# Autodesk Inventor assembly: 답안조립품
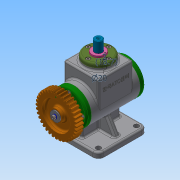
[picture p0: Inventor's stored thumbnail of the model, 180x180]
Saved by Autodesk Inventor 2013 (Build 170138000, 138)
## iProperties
Created: 2019-01
Part Number: 답안조립품
Document SubType Name: Assembly
Designer: Administrator
Author: Administrator
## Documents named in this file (18)
- C:\Users\Administrator\Desktop\390107V1001\답안조립품.iam
- C:\Users\Administrator\Desktop\390107V1001\본체.ipt
- C:\Users\Administrator\Desktop\390107V1001\뒤커버.ipt
- C:\Users\Administrator\Desktop\390107V1001\멈춤링.ipt
- C:\Users\Administrator\Desktop\390107V1001\베어링 6203.ipt
- C:\Users\Administrator\Desktop\390107V1001\볼트 M4.ipt
- C:\Users\Administrator\Desktop\390107V1001\부시.ipt
- C:\Users\Administrator\Desktop\390107V1001\상부커버.ipt
- C:\Users\Administrator\Desktop\390107V1001\스퍼기어.ipt
- C:\Users\Administrator\Desktop\390107V1001\스프링와셔.ipt
- C:\Users\Administrator\Desktop\390107V1001\스프링조립용 와셔.ipt
- C:\Users\Administrator\Desktop\390107V1001\슬라이더.ipt
- C:\Users\Administrator\Desktop\390107V1001\앞커버.ipt
- C:\Users\Administrator\Desktop\390107V1001\오일 실 17 30 5.ipt
- C:\Users\Administrator\Desktop\390107V1001\키 4x4x12.ipt
- C:\Users\Administrator\Desktop\390107V1001\편심축.ipt
- C:\Users\Administrator\Desktop\390107V1001\평와셔.ipt
- C:\Users\Administrator\Desktop\390107V1001\가변스프링.ipt
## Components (1 placed, 1 different names)
1. 가변스프링:1
